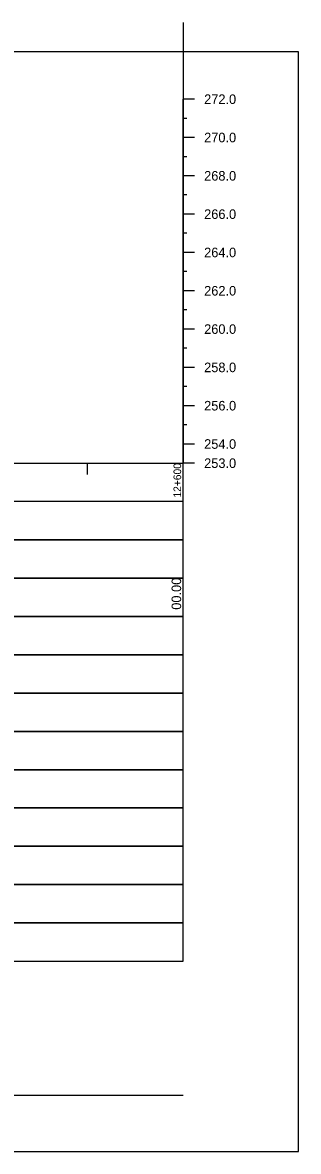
# Model space of a CAD drawing. Extents: x 6445630 to 6518227, y 5499240 to 5511716.
# Drawn here: x 6454589.3 to 6454661.3, y 5508061.6 to 5508356.3 of the extents above; entities that cross this region are included whole.
import ezdxf

# ---------------------------------------------------------------- set-up
doc = ezdxf.new("R2010")
doc.units = 0
for name, color, linetype in [('TOR_PROF-tabelka-geometria T1', 7, 'Continuous'), ('TOR_PROF-tabelka-odleglosci T1', 7, 'Continuous'), ('TOR_PROF-tabelka-pochylenia proj T1', 7, 'Continuous'), ('TOR_PROF-tabelka-rodzaj rowu T1', 7, 'Continuous'), ('TOR_PROF-tabelka-rowyT1', 7, 'Continuous'), ('TOR_PROF-tabelka-rurociagi T1', 7, 'Continuous'), ('TOR_PROF-tabelka-rzedne istn T1', 7, 'Continuous'), ('TOR_PROF-tabelka-rzedne proj T1', 7, 'Continuous'), ('TOR_PROF-tabelka-teren istniejacy T1', 7, 'Continuous'), ('TOR_PROF-tabelka-warstwa ochronna T1', 7, 'Continuous'), ('TOR_PROF-tor projektowany', 7, 'Continuous'), ('TOR_PROF-uklad odniesienia', 7, 'Continuous'), ('TOR_PROF-warstwa ochronna', 7, 'Continuous'), ('TOR_RAMKI-MASKA WYCIECIA', 7, 'Continuous')]:
    doc.layers.add(name, color=color, linetype=linetype)

msp = doc.modelspace()

# ---------------------------------------------------------------- linework, layer by layer
at = {"layer": 'TOR_PROF-tabelka-geometria T1'}
msp.add_lwpolyline([(6452331.21, 5508076.29), (6454631.21, 5508076.29)], dxfattribs=at)
at = {"layer": 'TOR_PROF-tabelka-odleglosci T1'}
msp.add_lwpolyline([(6452331.21, 5508201.29), (6454631.21, 5508201.29), (6454631.21, 5508211.29), (6452331.21, 5508211.29)], close=True, dxfattribs=at)
msp.add_lwpolyline([(6454631.21, 5508201.29), (6454631.21, 5508211.29)], dxfattribs=at)
at = {"layer": 'TOR_PROF-tabelka-pochylenia proj T1'}
msp.add_lwpolyline([(6452331.21, 5508221.29), (6454631.21, 5508221.29), (6454631.21, 5508231.29), (6452331.21, 5508231.29)], close=True, dxfattribs=at)
at = {"layer": 'TOR_PROF-tabelka-rodzaj rowu T1'}
for points in [[(6452331.21, 5508151.29), (6454631.21, 5508151.29), (6454631.21, 5508161.29), (6452331.21, 5508161.29)], [(6452331.21, 5508131.29), (6454631.21, 5508131.29), (6454631.21, 5508141.29), (6452331.21, 5508141.29)], [(6452331.21, 5508131.29), (6454631.21, 5508131.29), (6454631.21, 5508141.29), (6452331.21, 5508141.29)]]:
    msp.add_lwpolyline(points, close=True, dxfattribs=at)
msp.add_lwpolyline([(6454631.21, 5508131.29), (6454631.21, 5508141.29)], dxfattribs=at)
at = {"layer": 'TOR_PROF-tabelka-rowyT1'}
msp.add_lwpolyline([(6452331.21, 5508161.29), (6454631.21, 5508161.29), (6454631.21, 5508171.29), (6452331.21, 5508171.29)], close=True, dxfattribs=at)
at = {"layer": 'TOR_PROF-tabelka-rurociagi T1'}
msp.add_lwpolyline([(6452331.21, 5508141.29), (6454631.21, 5508141.29), (6454631.21, 5508151.29), (6452331.21, 5508151.29)], close=True, dxfattribs=at)
msp.add_lwpolyline([(6452331.21, 5508141.29), (6454631.21, 5508141.29), (6454631.21, 5508151.29), (6452331.21, 5508151.29)], close=True, dxfattribs=at)
msp.add_lwpolyline([(6454631.21, 5508141.29), (6454631.21, 5508151.29)], dxfattribs=at)
at = {"layer": 'TOR_PROF-tabelka-rzedne istn T1'}
msp.add_lwpolyline([(6452331.21, 5508191.29), (6454631.21, 5508191.29), (6454631.21, 5508201.29), (6452331.21, 5508201.29)], close=True, dxfattribs=at)
msp.add_lwpolyline([(6454631.21, 5508191.29), (6454631.21, 5508201.29)], dxfattribs=at)
at = {"layer": 'TOR_PROF-tabelka-rzedne proj T1'}
msp.add_lwpolyline([(6452331.21, 5508211.29), (6454631.21, 5508211.29), (6454631.21, 5508221.29), (6452331.21, 5508221.29)], close=True, dxfattribs=at)
msp.add_lwpolyline([(6454631.21, 5508211.29), (6454631.21, 5508221.29)], dxfattribs=at)
at = {"layer": 'TOR_PROF-tabelka-teren istniejacy T1'}
for points in [[(6452331.21, 5508181.29), (6454631.21, 5508181.29), (6454631.21, 5508191.29), (6452331.21, 5508191.29)], [(6452331.21, 5508171.29), (6454631.21, 5508171.29), (6454631.21, 5508181.29), (6452331.21, 5508181.29)], [(6452331.21, 5508171.29), (6454631.21, 5508171.29), (6454631.21, 5508181.29), (6452331.21, 5508181.29)]]:
    msp.add_lwpolyline(points, close=True, dxfattribs=at)
for points in [[(6454631.21, 5508181.29), (6454631.21, 5508191.29)], [(6454631.21, 5508171.29), (6454631.21, 5508181.29)], [(6454631.21, 5508171.29), (6454631.21, 5508181.29)]]:
    msp.add_lwpolyline(points, dxfattribs=at)
at = {"layer": 'TOR_PROF-tabelka-warstwa ochronna T1'}
msp.add_lwpolyline([(6452331.21, 5508121.29), (6454631.21, 5508121.29), (6454631.21, 5508131.29), (6452331.21, 5508131.29)], close=True, dxfattribs=at)
at = {"layer": 'TOR_PROF-tor projektowany'}
msp.add_lwpolyline([(6454631.21, 5508356.29), (6454631.21, 5508246.29), (6454631.21, 5508241.29), (6454631.21, 5508241.29)], dxfattribs=at)
at = {"layer": 'TOR_PROF-uklad odniesienia'}
for p, q in [((6454631.21, 5508241.29), (6454631.21, 5508336.29)), ((6454634.21, 5508336.29), (6454631.21, 5508336.29)), ((6454634.21, 5508336.29), (6454631.21, 5508336.29)), ((6454632.21, 5508331.29), (6454631.21, 5508331.29)), ((6454634.21, 5508326.29), (6454631.21, 5508326.29)), ((6454632.21, 5508321.29), (6454631.21, 5508321.29)), ((6454634.21, 5508316.29), (6454631.21, 5508316.29)), ((6454632.21, 5508311.29), (6454631.21, 5508311.29)), ((6454634.21, 5508306.29), (6454631.21, 5508306.29)), ((6454632.21, 5508301.29), (6454631.21, 5508301.29)), ((6454634.21, 5508296.29), (6454631.21, 5508296.29)), ((6454632.21, 5508291.29), (6454631.21, 5508291.29)), ((6454634.21, 5508286.29), (6454631.21, 5508286.29)), ((6454632.21, 5508281.29), (6454631.21, 5508281.29)), ((6454634.21, 5508276.29), (6454631.21, 5508276.29)), ((6454632.21, 5508271.29), (6454631.21, 5508271.29)), ((6454634.21, 5508266.29), (6454631.21, 5508266.29)), ((6454632.21, 5508261.29), (6454631.21, 5508261.29)), ((6454634.21, 5508256.29), (6454631.21, 5508256.29)), ((6454632.21, 5508251.29), (6454631.21, 5508251.29)), ((6454634.21, 5508246.29), (6454631.21, 5508246.29)), ((6452331.21, 5508241.29), (6454631.21, 5508241.29)), ((6454606.21, 5508238.29), (6454606.21, 5508241.29)), ((6454634.21, 5508241.29), (6454631.21, 5508241.29)), ((6454631.21, 5508231.29), (6454631.21, 5508241.29))]:
    msp.add_line(p, q, dxfattribs=at)
at = {"layer": 'TOR_PROF-warstwa ochronna'}
msp.add_lwpolyline([(6452331.21, 5508111.29), (6454631.21, 5508111.29), (6454631.21, 5508121.29), (6452331.21, 5508121.29)], close=True, dxfattribs=at)
at = {"layer": 'TOR_RAMKI-MASKA WYCIECIA'}
msp.add_lwpolyline([(6452261.34, 5508061.65), (6454661.34, 5508061.65), (6454661.34, 5508348.65), (6452261.34, 5508348.65)], close=True, dxfattribs=at)

# ---------------------------------------------------------------- texts
at = {"layer": 'TOR_PROF-tabelka-odleglosci T1'}
msp.add_text('00.00', height=2.5, rotation=90, dxfattribs=at).set_placement((6454630.71, 5508203.03))
at = {"layer": 'TOR_PROF-uklad odniesienia'}
for s, p in [('272.0', (6454636.71, 5508335.04)), ('272.0', (6454636.71, 5508335.04)), ('270.0', (6454636.71, 5508325.04)), ('268.0', (6454636.71, 5508315.04)), ('266.0', (6454636.71, 5508305.04)), ('264.0', (6454636.71, 5508295.04)), ('262.0', (6454636.71, 5508285.04)), ('260.0', (6454636.71, 5508275.04)), ('258.0', (6454636.71, 5508265.04)), ('256.0', (6454636.71, 5508255.04)), ('254.0', (6454636.71, 5508245.04)), ('253.0', (6454636.71, 5508240.04))]:
    msp.add_text(s, height=2.5, dxfattribs=at).set_placement(p)
msp.add_text('12+600', height=2, rotation=90, dxfattribs=at).set_placement((6454630.71, 5508232.31))

doc.saveas('drawing.dxf')
